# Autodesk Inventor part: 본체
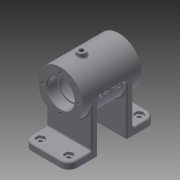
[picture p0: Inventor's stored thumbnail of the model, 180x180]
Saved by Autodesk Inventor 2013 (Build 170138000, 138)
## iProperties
Created: 2017-02
Part Number: 본체
Material: 일반
Document SubType Name: Modeling
Designer: Administrator
Density: 1 g/cm^3
Author: Administrator
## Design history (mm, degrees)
sketch "스케치1"
  geometry: C1 r 27 at (0, 0); 1 further point
  constraints: 1 centre point, 1 coincident
  dimensions: "d0" = 54 diameter of C1
extrude "돌출1" new body sketch "스케치1" stored distance "d2" = 70; taper "d3" = 0 deg
node "작업 평면1"
sketch "스케치2"
  geometry: L1 (-27, 52)-(27, 52); L2 (27, 52)-(27, -52); L3 (27, -52)-(-27, -52); L4 (-27, -52)-(-27, 52); L5 (-27, 17)-(27, 17); L6 (27, 17)-(27, -17); L7 (27, -17)-(-27, -17); L8 (-27, -17)-(-27, 17); 2 further points
  constraints: 16 end point, 4 parallel, 2 horizontal, 2 perpendicular, 2 point on line, 1 coincident
  dimensions: "d5" = 104 distance of L1.end L2.end; "d7" = 54 distance of L1.start L1.end; "d8" = 52 vertical distance of point (0, 0) L1.end; "d13" = 17 vertical distance of L5.end point (0, 0); "d14" = 17 vertical distance of L6.end point (0, 0); "d15" = 27 horizontal distance of L1.start point (0, 0)
extrude "돌출3" join sketch "스케치2" distance "d16" = 8; taper "d17" = 0 deg
sketch "스케치4"
  geometry: L1 (-35, 27)-(-35, -27) reference; L2 (35, -27)-(35, 27) reference; L3 (-35, -27)-(-35, 27) reference; L4 (-35, 27)-(35, 27) reference; L5 (35, 27)-(35, -27) reference; L6 (35, -27)-(-35, -27) reference; L7 (-52, -60)-(-52, -52) reference; L8 (-52, -52)-(-17, -52) reference; L9 (-17, -52)-(-17, -60) reference; L10 (-17, -60)-(-52, -60) reference; L11 (17, -60)-(17, -52) reference; L12 (17, -52)-(52, -52) reference; L13 (52, -52)-(52, -60) reference; L14 (52, -60)-(17, -60) reference; L15 (-35, 0)-(-23, 0); L16 (-23, 0)-(-23, 15.7); L17 (-23.3, 16)-(-35, 16); L18 (-35, 16)-(-35, 0); L19 (-23, 0)-(-20, 0); L20 (-20, 0)-(-20, 14); L21 (-20, 14)-(-23, 14); L22 (-23, 14)-(-23, 0); L23 (-20, 0)-(20, 0); L24 (20, 0)-(20, 19); L25 (17, 22)-(-17, 22); L26 (-20, 19)-(-20, 0); L27 (20, 0)-(23, 0); L28 (23, 0)-(23, 14); L29 (23, 14)-(20, 14); L30 (20, 14)-(20, 0); L31 (23, 0)-(35, 0); L32 (35, 0)-(35, 16); L33 (35, 16)-(23.3, 16); L34 (23, 15.7)-(23, 0); A1 r 3 centre (-17, 19) between (-17, 22) and (-20, 19); A2 r 3 centre (17, 19) between (20, 19) and (17, 22); A3 r 0.3 centre (-23.3, 15.7) between (-23, 15.7) and (-23.3, 16); A4 r 0.3 centre (23.3, 15.7) between (23.3, 16) and (23, 15.7); 6 further points
  constraints: 40 end point, 10 parallel, 9 point on line, 8 point on circle, 8 tangent, 5 horizontal, 5 perpendicular, 4 centre point, 2 equal radius, 2 midpoint, 1 vertical alignment
  dimensions: "d18" = 32 diameter of L17 L15; "d20" = 28 diameter of L21 L19; "d21" = 44 diameter of L25 L23; "d22" = 28 diameter of L29 L27; "d23" = 32 diameter of L33 L31; "d24" = 12 distance of point (-23, 16) L17.end; "d25" = 40 distance between parallel lines of L24 L20; "d26" = 12 distance between parallel lines of L32 L28; "d28" = 3 radius of A1; "d29" = 0.3 radius of A3
revolve "회전1" sketch "스케치4" stored, may be unused: angle "d27" = 90 deg
chamfer "모따기1" distance "d30" = 1; stored, may be unused: second distance "d31" = 2, angle "d32" = 45 deg
chamfer "모따기2" distance "d33" = 1; stored, may be unused: second distance "d34" = 2, angle "d35" = 45 deg
sketch "스케치5"
  geometry: L1 (0, 0)-(0, 21); C1 r 17 at (0, 0) reference; 1 further point
  constraints: 2 end point, 1 coincident, 1 vertical
  dimensions: "d36" = 21 distance of L1.start L1.end
hole "구멍1" sketch "스케치5" at (0, 21) diameter "d37" = 3.242; stored, may be unused: countersink angle "d41" = 90 deg, drill point angle "d43" = 118 deg; dims "d38" = 8, "d39" = 4, "d40" = 2, "d42" = 10
node "작업 평면2"
sketch "스케치6"
  geometry: L1 (-27, -35)-(27, -35) reference; L2 (0, -35)-(0, -10); C1 r 5 at (0, -10); 1 further point
  constraints: 2 end point, 1 centre point, 1 coincident, 1 midpoint, 1 perpendicular
  dimensions: "d48" = 25 distance of L2.start L2.end; "d50" = 10 diameter of C1
extrude "돌출4" join sketch "스케치6" stored distance "d51" = 8; taper "d52" = 0 deg
sketch "스케치7"
  geometry: C1 r 5 at (0, 0) reference; 2 further points
  constraints: 1 coincident
hole "구멍2" sketch "스케치7" at (0, 0) diameter "d53" = 5.188; stored, may be unused: countersink angle "d57" = 90 deg, drill point angle "d59" = 118 deg; dims "d54" = 10, "d55" = 4, "d56" = 2, "d58" = 10
node "작업 평면3"
sketch "스케치8"
  geometry: L1 (0, 0)-(0, 50.474); L2 (0, 0)-(-16.339, 25.16)
  constraints: 4 end point, 1 vertical
  dimensions: "d61" = 33 deg angle of L1 L2; "d62" = 30 distance of L1.start L2.end
node "작업 평면4"
  node "작업점1"
sketch "스케치9"
  geometry: C1 r 6 at (0, 0); 1 further point
  constraints: 1 centre point, 1 coincident
  dimensions: "d63" = 12 diameter of C1
extrude "돌출5" join sketch "스케치9" stored distance "d65" = 8; taper "d66" = 0 deg
sketch "스케치10"
  geometry: C1 r 6 at (0, 0) reference; 1 further point
  constraints: 1 coincident
hole "구멍3" sketch "스케치10" at (0, 0) diameter "d67" = 5.188; stored, may be unused: countersink angle "d71" = 90 deg, drill point angle "d73" = 118 deg; dims "d68" = 8, "d69" = 4, "d70" = 2, "d72" = 10
sketch "스케치11"
  geometry: L1 (-27, 17)-(27, 17) reference; L2 (27, 17)-(27, 52) reference; L3 (-27, 17)-(27, 17); L4 (27, 17)-(27, 25); L5 (27, 25)-(-27, 25); L6 (-27, 25)-(-27, 17); L7 (-27, -17)-(27, -17) reference; L8 (27, -52)-(27, -17) reference; L9 (-27, -52)-(27, -52) reference; L10 (-27, -17)-(-27, -52) reference; L11 (-27, -17)-(27, -17); L12 (27, -17)-(27, -25); L13 (27, -25)-(-27, -25); L14 (-27, -25)-(-27, -17); 1 further point
  constraints: 16 end point, 4 parallel, 2 horizontal, 2 perpendicular, 2 point on line
  dimensions: "d74" = 8 distance of L3.end L4.end; "d76" = 8 distance of L11.end L12.end
extrude "돌출6" join sketch "스케치11" stored distance "d77" = 8; taper "d78" = 0 deg
fillet "모깎기1" dims "d79" = 10
sketch "스케치13"
  geometry: L1 (-17, -52)-(17, -52) reference; L2 (-27, -17)-(-27, -42) reference; L3 (-27, -17)-(27, -17) reference; L4 (27, -42)-(27, -17) reference; A1 r 10 centre (-17, 42) between (-17, 52) and (-27, 42) reference; A2 r 10 centre (17, 42) between (27, 42) and (17, 52) reference; A3 r 10 centre (17, -42) between (17, -52) and (27, -42) reference; A4 r 10 centre (-17, -42) between (-27, -42) and (-17, -52) reference; 5 further points
  constraints: 4 coincident
hole "구멍4" sketch "스케치13" at (-17, 42), (17, 42), (17, -42), (-17, -42) diameter "d80" = 5; stored, may be unused: countersink angle "d84" = 90 deg, drill point angle "d86" = 118 deg; dims "d81" = 8, "d82" = 9, "d83" = 3, "d85" = 10
sketch "스케치14"
  geometry: L1 (-12.339, -39.703)-(-12.681, -44.888); L2 (-12.681, -44.888)-(-17.342, -47.185); L3 (-17.342, -47.185)-(-21.661, -44.297); L4 (-21.661, -44.297)-(-21.319, -39.112); L5 (-21.319, -39.112)-(-16.658, -36.815); L6 (-16.658, -36.815)-(-12.339, -39.703); L7 (21.661, -39.703)-(21.319, -44.888); L8 (21.319, -44.888)-(16.658, -47.185); L9 (16.658, -47.185)-(12.339, -44.297); L10 (12.339, -44.297)-(12.681, -39.112); L11 (12.681, -39.112)-(17.342, -36.815); L12 (17.342, -36.815)-(21.661, -39.703); L13 (-12.339, 44.297)-(-12.681, 39.112); L14 (-12.681, 39.112)-(-17.342, 36.815); L15 (-17.342, 36.815)-(-21.661, 39.703); L16 (-21.661, 39.703)-(-21.319, 44.888); L17 (-21.319, 44.888)-(-16.658, 47.185); L18 (-16.658, 47.185)-(-12.339, 44.297); L19 (21.5, 44.888)-(21.751, 39.547); L20 (21.751, 39.547)-(17.251, 36.659); L21 (17.251, 36.659)-(12.5, 39.112); L22 (12.5, 39.112)-(12.249, 44.453); L23 (12.249, 44.453)-(16.749, 47.341); L24 (16.749, 47.341)-(21.5, 44.888); C1 r 4.5 at (17, 42) reference; A1 r 10 centre (17, -42) between (17, -52) and (27, -42) reference; 11 further points
  constraints: 48 end point, 4 coincident, 3 midpoint, 58 other
extrude "돌출7" cut sketch "스케치14" distance "d87" = 3; taper "d88" = 0 deg
node "작업 평면5"
sketch "스케치15"
  geometry: L1 (-35, 27)-(-35, -27) reference; L2 (-35, 27)-(35, 27) reference; L3 (-17.123, 2.191)-(17.123, 2.191); L4 (17.123, 2.191)-(17.123, -2.191); L5 (17.123, -2.191)-(-17.123, -2.191); L6 (-17.123, -2.191)-(-17.123, 2.191); L7 (0, 2.191)-(0, -2.191); L8 (-17.123, 0)-(17.123, 0); 2 further points
  constraints: 5 midpoint, 4 end point, 1 coincident, 2 other
feature "엠보싱1" sketch "스케치15" dims "d90" = 0.5, "d91" = 0
fillet "모깎기2" dims "d92" = 2
fillet "모깎기3" dims "d93" = 2
node "솔리드1"
pattern_circular "원형 패턴1" dims angle "d45" = 360 deg
mirror "대칭1"
node "투영된 루프1"
node "투영된 루프2"
node "투영된 루프3"
node "절단 모서리 투영1"
other parameters: "d47" = -92, "d60" = -35
